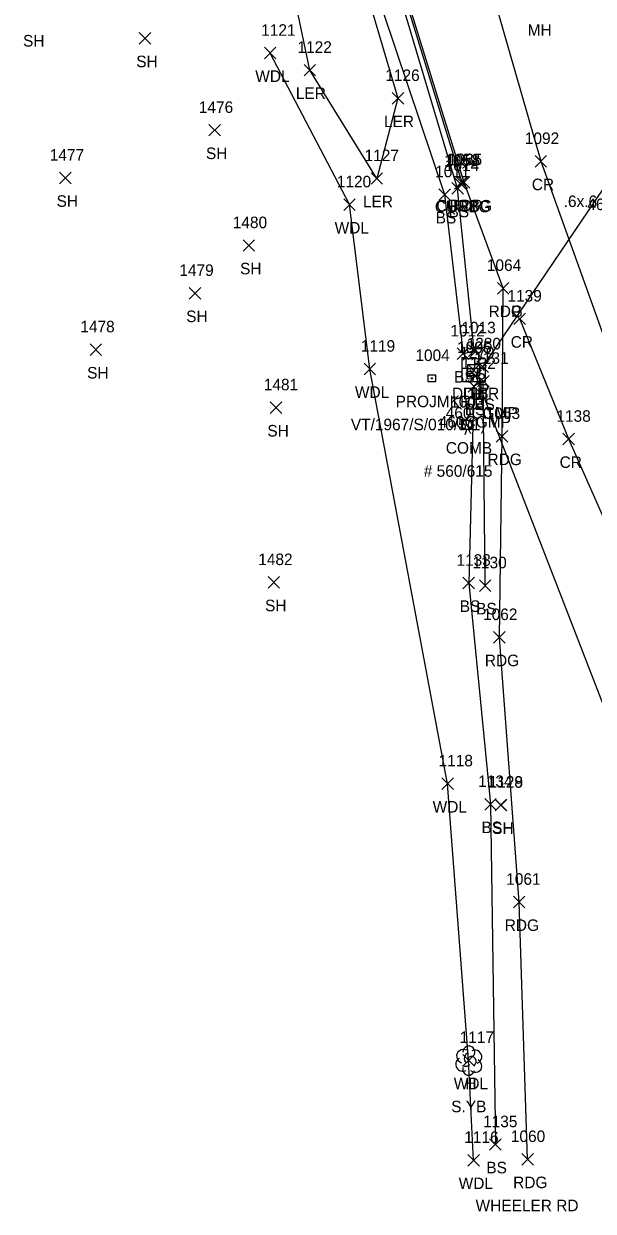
# Model space of a CAD drawing. Extents: x 462930 to 463548, y 29607 to 30453.
# Drawn here: x 463323.7 to 463353.8, y 29942.1 to 30004.8 of the extents above; entities that cross this region are included whole.
import ezdxf

# ---------------------------------------------------------------- set-up
doc = ezdxf.new("R2010")
doc.units = 0
for name, color, linetype in [('D_A', 7, 'Continuous'), ('D_C', 7, 'Continuous'), ('D_I', 7, 'Continuous'), ('D_TIC', 7, 'Continuous'), ('DCP', 7, 'Continuous'), ('DS', 7, 'Continuous'), ('L_A', 7, 'Continuous'), ('L_C', 7, 'Continuous'), ('L_I', 7, 'Continuous'), ('L_TIC', 7, 'Continuous'), ('LARO', 7, 'Continuous'), ('LAWA', 7, 'Continuous'), ('LELB', 7, 'Continuous'), ('LTD', 7, 'Continuous'), ('P_A', 7, 'Continuous'), ('P_C', 7, 'Continuous'), ('P_I', 7, 'Continuous'), ('P_TIC', 7, 'Continuous'), ('PET', 7, 'Continuous'), ('PEU', 7, 'Continuous'), ('PRC', 7, 'Continuous'), ('R_A', 7, 'Continuous'), ('R_I', 7, 'Continuous'), ('R_TIC', 7, 'Continuous'), ('RC', 7, 'Continuous'), ('S_A', 7, 'Continuous'), ('S_C', 7, 'Continuous'), ('S_I', 7, 'Continuous'), ('SRM', 7, 'Continuous'), ('U_A', 7, 'Continuous'), ('U_C', 7, 'Continuous'), ('U_I', 7, 'Continuous'), ('UP', 7, 'Continuous')]:
    doc.layers.add(name, color=color, linetype=linetype)

msp = doc.modelspace()

# ---------------------------------------------------------------- linework, layer by layer
at = {"layer": 'D_TIC'}
for points in [[(463347.198, 29986.179), (463347.808, 29986.789)], [(463347.808, 29986.179), (463347.198, 29986.789)], [(463347.667, 29986.37), (463348.277, 29986.98)], [(463348.277, 29986.37), (463347.667, 29986.98)], [(463347.301, 29985.894), (463347.911, 29986.504)], [(463347.911, 29985.894), (463347.301, 29986.504)]]:
    msp.add_lwpolyline(points, dxfattribs=at)
at = {"layer": 'DCP'}
for points in [[(463347.972, 29986.675), (463355.452, 29997.69)], [(463357.242, 29961.347), (463347.606, 29986.199)]]:
    msp.add_lwpolyline(points, dxfattribs=at)
at = {"layer": 'DS'}
for p, q in [((463346.89, 29987.1), (463348.109, 29987.1)), ((463346.89, 29985.881), (463346.893, 29987.1)), ((463347.195, 29986.795), (463347.804, 29986.795)), ((463347.195, 29986.186), (463347.195, 29986.795)), ((463347.804, 29986.795), (463347.804, 29986.186)), ((463348.109, 29987.1), (463348.109, 29985.881)), ((463347.804, 29986.186), (463347.195, 29986.186)), ((463347.5, 29986.494), (463347.5, 29986.494)), ((463348.109, 29985.881), (463346.89, 29985.881)), ((463347.652, 29985.881), (463347.804, 29985.881))]:
    msp.add_line(p, q, dxfattribs=at)
at = {"layer": 'L_TIC'}
for points in [[(463329.836, 30003.714), (463330.446, 30004.324)], [(463330.446, 30003.714), (463329.836, 30004.324)], [(463336.448, 30002.937), (463337.058, 30003.547)], [(463337.058, 30002.937), (463336.448, 30003.547)], [(463338.538, 30002.036), (463339.148, 30002.646)], [(463339.148, 30002.036), (463338.538, 30002.646)], [(463343.192, 30000.548), (463343.802, 30001.158)], [(463343.802, 30000.548), (463343.192, 30001.158)], [(463333.517, 29998.863), (463334.127, 29999.473)], [(463334.127, 29998.863), (463333.517, 29999.473)], [(463325.629, 29996.34), (463326.239, 29996.95)], [(463326.239, 29996.34), (463325.629, 29996.95)], [(463342.081, 29996.314), (463342.691, 29996.924)], [(463342.691, 29996.314), (463342.081, 29996.924)], [(463346.341, 29995.788), (463346.951, 29996.398)], [(463346.951, 29995.788), (463346.341, 29996.398)], [(463340.638, 29994.93), (463341.248, 29995.54)], [(463341.248, 29994.93), (463340.638, 29995.54)], [(463345.66, 29995.462), (463346.27, 29996.072)], [(463346.27, 29995.462), (463345.66, 29996.072)], [(463335.318, 29992.774), (463335.928, 29993.384)], [(463335.928, 29992.774), (463335.318, 29993.384)], [(463332.472, 29990.25), (463333.082, 29990.86)], [(463333.082, 29990.25), (463332.472, 29990.86)], [(463327.242, 29987.27), (463327.852, 29987.88)], [(463327.852, 29987.27), (463327.242, 29987.88)], [(463346.632, 29987.055), (463347.242, 29987.665)], [(463347.242, 29987.055), (463346.632, 29987.665)], [(463347.216, 29987.22), (463347.826, 29987.83)], [(463347.826, 29987.22), (463347.216, 29987.83)], [(463341.709, 29986.248), (463342.319, 29986.858)], [(463342.319, 29986.248), (463341.709, 29986.858)], [(463347.698, 29985.606), (463348.308, 29986.216)], [(463348.308, 29985.606), (463347.698, 29986.216)], [(463347.199, 29985.336), (463347.809, 29985.946)], [(463347.809, 29985.336), (463347.199, 29985.946)], [(463336.758, 29984.207), (463337.368, 29984.817)], [(463337.368, 29984.207), (463336.758, 29984.817)], [(463336.638, 29974.976), (463337.248, 29975.586)], [(463337.248, 29974.976), (463336.638, 29975.586)], [(463346.933, 29974.94), (463347.543, 29975.55)], [(463347.543, 29974.94), (463346.933, 29975.55)], [(463347.797, 29974.808), (463348.407, 29975.418)], [(463348.407, 29974.808), (463347.797, 29975.418)], [(463345.813, 29964.342), (463346.423, 29964.952)], [(463346.423, 29964.342), (463345.813, 29964.952)], [(463348.081, 29963.256), (463348.691, 29963.866)], [(463348.691, 29963.256), (463348.081, 29963.866)], [(463348.628, 29963.222), (463349.238, 29963.832)], [(463349.238, 29963.222), (463348.628, 29963.832)], [(463348.632, 29963.21), (463349.242, 29963.82)], [(463349.242, 29963.21), (463348.632, 29963.82)], [(463346.926, 29949.729), (463347.536, 29950.339)], [(463347.536, 29949.729), (463346.926, 29950.339)], [(463348.336, 29945.283), (463348.946, 29945.893)], [(463348.946, 29945.283), (463348.336, 29945.893)], [(463347.187, 29944.452), (463347.797, 29945.062)], [(463347.797, 29944.452), (463347.187, 29945.062)]]:
    msp.add_lwpolyline(points, dxfattribs=at)
at = {"layer": 'LARO'}
for points in [[(463338.843, 30002.341), (463337.309, 30009.673), (463337.417, 30015.173), (463340.502, 30011.002), (463343.497, 30000.853), (463342.386, 29996.619)], [(463342.386, 29996.619), (463338.843, 30002.341)]]:
    msp.add_lwpolyline(points, dxfattribs=at)
at = {"layer": 'LAWA'}
msp.add_lwpolyline([(463347.492, 29944.757), (463347.231, 29950.034), (463346.118, 29964.647), (463342.014, 29986.553), (463340.943, 29995.235), (463336.753, 30003.242)], dxfattribs=at)
at = {"layer": 'LELB'}
for points in [[(463338.373, 30022.22), (463340.767, 30011.24), (463345.965, 29995.767), (463346.937, 29987.36), (463347.521, 29987.525), (463346.646, 29996.093), (463342.063, 30011.435), (463339.344, 30022.565), (463336.301, 30037.573), (463333.414, 30053.384), (463330.633, 30068.275), (463328.629, 30079.728), (463328.086, 30089.487), (463328.627, 30097.184), (463330.299, 30105.361), (463329.682, 30105.522), (463327.994, 30097.289)], [(463348.102, 29975.113), (463348.003, 29985.911), (463347.504, 29985.641), (463347.238, 29975.245), (463348.386, 29963.561), (463348.641, 29945.588)]]:
    msp.add_lwpolyline(points, dxfattribs=at)
at = {"layer": 'LTD'}
msp.add_line((463347.231, 29950.034), (463347.231, 29950.034), dxfattribs=at)
msp.add_line((463347.231, 29950.034), (463347.231, 29950.034), dxfattribs=at)
msp.add_arc((463347.245, 29950.471), 0.319, 335.52715, 180.95627, dxfattribs=at)
for centre, major_axis, ratio, start_param, end_param in [((463346.99, 29950.237), (0.369, -0.156), 0.895232, 1.570796, 4.712389), ((463347.167, 29950.174), (-0.063, -0.241), 0.645439, 3.141593, 6.283185), ((463347.548, 29950.212), (-0.348, -0.147), 0.949671, 1.570796, 4.712389), ((463346.901, 29949.818), (0.178, -0.317), 0.959034, 3.141593, 6.283185), ((463347.091, 29949.805), (-0.19, -0.025), 0.423636, 0, 3.141593), ((463347.383, 29949.983), (-0.152, 0.203), 0.989748, 3.141593, 6.283185), ((463347.536, 29949.78), (-0.332, 0.241), 0.841452, 1.570796, 4.712389), ((463347.231, 29949.577), (0.081, 0.323), 0.942809, 1.570796, 4.712389)]:
    msp.add_ellipse(centre, major_axis=major_axis, ratio=ratio, start_param=start_param, end_param=end_param, dxfattribs=at)
at = {"layer": 'P_TIC'}
for points in [[(463350.739, 29997.219), (463351.349, 29997.829)], [(463351.349, 29997.219), (463350.739, 29997.829)], [(463346.685, 29996.104), (463347.295, 29996.714)], [(463347.295, 29996.104), (463346.685, 29996.714)], [(463348.747, 29990.515), (463349.357, 29991.125)], [(463349.357, 29990.515), (463348.747, 29991.125)], [(463348.747, 29990.515), (463349.357, 29991.125)], [(463349.357, 29990.515), (463348.747, 29991.125)], [(463349.625, 29988.898), (463350.235, 29989.508)], [(463350.235, 29988.898), (463349.625, 29989.508)], [(463348.688, 29982.693), (463349.298, 29983.303)], [(463349.298, 29982.693), (463348.688, 29983.303)], [(463352.209, 29982.546), (463352.819, 29983.156)], [(463352.819, 29982.546), (463352.209, 29983.156)], [(463348.547, 29972.073), (463349.157, 29972.683)], [(463349.157, 29972.073), (463348.547, 29972.683)], [(463349.597, 29958.088), (463350.207, 29958.698)], [(463350.207, 29958.088), (463349.597, 29958.698)], [(463350.042, 29944.5), (463350.652, 29945.11)], [(463350.652, 29944.5), (463350.042, 29945.11)]]:
    msp.add_lwpolyline(points, dxfattribs=at)
at = {"layer": 'PET'}
msp.add_lwpolyline([(463349.052, 29990.82), (463346.99, 29996.409), (463342.314, 30011.546), (463339.633, 30022.646), (463336.631, 30037.644), (463333.669, 30053.397), (463330.887, 30068.339), (463328.89, 30079.76), (463328.357, 30089.522), (463328.892, 30097.183), (463330.561, 30105.3)], dxfattribs=at)
at = {"layer": 'PEU'}
msp.add_lwpolyline([(463350.347, 29944.805), (463349.902, 29958.393), (463348.852, 29972.378), (463348.993, 29982.998), (463349.052, 29990.82)], dxfattribs=at)
at = {"layer": 'PRC'}
for points in [[(463337.978, 30112.385), (463335.087, 30099.771), (463333.576, 30084.385), (463334.686, 30068.796), (463337.03, 30053.748), (463339.908, 30038.01), (463343.632, 30023.045), (463346.617, 30012.904), (463351.044, 29997.524), (463354.76, 29987.177), (463360.584, 29974.202), (463367.548, 29960.534), (463374.695, 29948.349)], [(463361.503, 29963.111), (463356.689, 29973.422), (463352.514, 29982.851), (463349.93, 29989.203)]]:
    msp.add_lwpolyline(points, dxfattribs=at)
at = {"layer": 'R_TIC'}
for points in [[(463346.486, 29996.048), (463347.096, 29996.658)], [(463347.096, 29996.048), (463346.486, 29996.658)], [(463346.566, 29996.093), (463347.176, 29996.703)], [(463347.176, 29996.093), (463346.566, 29996.703)]]:
    msp.add_lwpolyline(points, dxfattribs=at)
at = {"layer": 'RC'}
msp.add_lwpolyline([(463330.433, 30105.335), (463330.506, 30105.311), (463328.851, 30097.179), (463328.319, 30089.513), (463328.85, 30079.744), (463330.845, 30068.328), (463333.629, 30053.397), (463336.583, 30037.649), (463339.548, 30022.613), (463342.224, 30011.501), (463346.871, 29996.398), (463346.791, 29996.353)], dxfattribs=at)
at = {"layer": 'SRM'}
msp.add_lwpolyline([(463345.097, 29986.252), (463345.479, 29986.252), (463345.479, 29985.87), (463345.097, 29985.87)], close=True, dxfattribs=at)
msp.add_circle((463345.288, 29986.061), 0.0254, dxfattribs=at)
at = {"layer": 'UP'}
for p, q in [((463346.874, 29983.351), (463346.874, 29983.859)), ((463346.874, 29983.859), (463347.382, 29983.859)), ((463347.204, 29984.113), (463347.128, 29983.859)), ((463347.382, 29983.859), (463347.382, 29983.351)), ((463347.382, 29983.351), (463346.874, 29983.351)), ((463347.052, 29983.097), (463347.128, 29983.351)), ((463347.128, 29983.605), (463347.128, 29983.605))]:
    msp.add_line(p, q, dxfattribs=at)
msp.add_circle((463347.128, 29983.605), 0.254, dxfattribs=at)

# ---------------------------------------------------------------- texts
at = {"layer": 'D_A'}
for s, height, p in [('DITHR', 0.6096, (463346.355, 29984.96)), ('DIB', 0.6096, (463346.925, 29984.96)), ('P', 0.61, (463347.782, 29985.151)), ('P', 0.61, (463347.416, 29984.675))]:
    msp.add_text(s, height=height, dxfattribs=at).set_placement(p)
at = {"layer": 'D_C'}
for s, p in [('.6x.6 M GRATE', (463352.25, 29995.11)), ('460CGMP', (463353.501, 29994.947)), ('460CGMP', (463346.021, 29983.932)), ('460CGMP', (463345.655, 29983.456))]:
    msp.add_text(s, height=0.6096, dxfattribs=at).set_placement(p)
at = {"layer": 'D_I'}
for s, p in [('1006', (463346.617, 29987.398)), ('1005', (463346.636, 29987.398)), ('1280', (463347.125, 29987.589)), ('1279', (463346.783, 29987.113))]:
    msp.add_text(s, height=0.6096, dxfattribs=at).set_placement(p)
at = {"layer": 'L_A'}
for s, height, p in [('SH', 0.6096, (463323.702, 30003.589)), ('SH', 0.6096, (463329.68, 30002.495)), ('WDL', 0.6096, (463335.966, 30001.718)), ('LER', 0.6096, (463338.106, 30000.817)), ('LER', 0.6096, (463342.76, 29999.329)), ('SH', 0.6096, (463333.361, 29997.644)), ('SH', 0.6096, (463325.473, 29995.121)), ('LER', 0.6096, (463341.649, 29995.095)), ('BS', 0.6096, (463346.171, 29994.569)), ('WDL', 0.6096, (463340.156, 29993.711)), ('BS', 0.6096, (463345.49, 29994.243)), ('SH', 0.6096, (463335.162, 29991.555)), ('SH', 0.6096, (463332.316, 29989.031)), ('SH', 0.6096, (463327.086, 29986.051)), ('BS', 0.6096, (463346.462, 29985.836)), ('BS', 0.6096, (463347.046, 29986.001)), ('WDL', 0.6096, (463341.227, 29985.029)), ('BS', 0.6096, (463347.528, 29984.387)), ('BS', 0.6096, (463347.029, 29984.117)), ('SH', 0.6096, (463336.602, 29982.988)), ('SH', 0.6096, (463336.482, 29973.757)), ('BS', 0.6096, (463346.763, 29973.721)), ('BS', 0.6096, (463347.627, 29973.589)), ('WDL', 0.6096, (463345.331, 29963.123)), ('BS', 0.6096, (463347.911, 29962.037)), ('SH', 0.6096, (463348.472, 29962.003)), ('SH', 0.6096, (463348.476, 29961.991)), ('WDL', 0.6096, (463346.444, 29948.51)), ('H', 0.61, (463347.058, 29948.51)), ('BS', 0.6096, (463348.166, 29944.064)), ('WDL', 0.6096, (463346.705, 29943.233))]:
    msp.add_text(s, height=height, dxfattribs=at).set_placement(p)
at = {"layer": 'L_C'}
msp.add_text('S.YB', height=0.6096, dxfattribs=at).set_placement((463346.312, 29947.291))
at = {"layer": 'L_I'}
for s, p in [('1121', (463336.278, 30004.156)), ('1122', (463338.195, 30003.255)), ('1126', (463342.832, 30001.767)), ('1476', (463332.984, 30000.082)), ('1477', (463325.113, 29997.559)), ('1127', (463341.738, 29997.533)), ('1014', (463345.974, 29997.007)), ('1011', (463345.466, 29996.681)), ('1120', (463340.269, 29996.149)), ('1480', (463334.776, 29993.993)), ('1479', (463331.954, 29991.469)), ('1478', (463326.726, 29988.489)), ('1012', (463346.265, 29988.274)), ('1013', (463346.849, 29988.439)), ('1119', (463341.537, 29987.467)), ('1131', (463347.528, 29986.825)), ('1132', (463346.856, 29986.555)), ('1481', (463336.415, 29985.426)), ('1482', (463336.122, 29976.195)), ('1133', (463346.59, 29976.159)), ('1130', (463347.428, 29976.027)), ('1118', (463345.643, 29965.561)), ('1134', (463347.738, 29964.475)), ('1128', (463348.285, 29964.441)), ('1129', (463348.287, 29964.429)), ('1117', (463346.756, 29950.948)), ('1117', (463346.756, 29950.948)), ('1135', (463347.993, 29946.502)), ('1116', (463347, 29945.671))]:
    msp.add_text(s, height=0.6096, dxfattribs=at).set_placement(p)
at = {"layer": 'P_A'}
for s, p in [('CR', (463350.566, 29996)), ('RDP', (463346.224, 29994.885)), ('RDG', (463348.286, 29989.296)), ('RDP', (463348.286, 29989.296)), ('CR', (463349.452, 29987.679)), ('RDG', (463348.227, 29981.474)), ('CR', (463352.036, 29981.327)), ('RDG', (463348.086, 29970.854)), ('RDG', (463349.136, 29956.869)), ('RDG', (463349.581, 29943.281))]:
    msp.add_text(s, height=0.6096, dxfattribs=at).set_placement(p)
at = {"layer": 'P_C'}
msp.add_text('WHEELER RD', height=0.6096, dxfattribs=at).set_placement((463347.599, 29942.062))
at = {"layer": 'P_I'}
for s, p in [('1092', (463350.199, 29998.438)), ('1065', (463346.131, 29997.323)), ('1064', (463348.193, 29991.734)), ('1064', (463348.193, 29991.734)), ('1139', (463349.28, 29990.117)), ('1063', (463348.134, 29983.912)), ('1138', (463351.866, 29983.765)), ('1062', (463347.993, 29973.292)), ('1061', (463349.216, 29959.307)), ('1060', (463349.461, 29945.719))]:
    msp.add_text(s, height=0.6096, dxfattribs=at).set_placement(p)
at = {"layer": 'R_A'}
for p in [(463345.445, 29994.829), (463345.525, 29994.874)]:
    msp.add_text('CURBG', height=0.6096, dxfattribs=at).set_placement(p)
at = {"layer": 'R_I'}
for s, p in [('1059', (463345.944, 29997.267)), ('1058', (463346.026, 29997.312))]:
    msp.add_text(s, height=0.6096, dxfattribs=at).set_placement(p)
at = {"layer": 'S_A'}
msp.add_text('PROJMKR', height=0.6096, dxfattribs=at).set_placement((463343.375, 29984.537))
at = {"layer": 'S_C'}
msp.add_text('VT/1967/S/010/5(1)', height=0.6096, dxfattribs=at).set_placement((463341.011, 29983.318))
at = {"layer": 'S_I'}
msp.add_text('1004', height=0.6096, dxfattribs=at).set_placement((463344.419, 29986.975))
at = {"layer": 'U_A'}
for s, p in [('MH', (463350.348, 30004.156)), ('COMB', (463346.026, 29982.081))]:
    msp.add_text(s, height=0.6096, dxfattribs=at).set_placement(p)
at = {"layer": 'U_C'}
msp.add_text('# 560/615', height=0.6096, dxfattribs=at).set_placement((463344.862, 29980.862))
at = {"layer": 'U_I'}
msp.add_text('1003', height=0.6096, dxfattribs=at).set_placement((463346.259, 29984.519))

doc.saveas('drawing.dxf')
